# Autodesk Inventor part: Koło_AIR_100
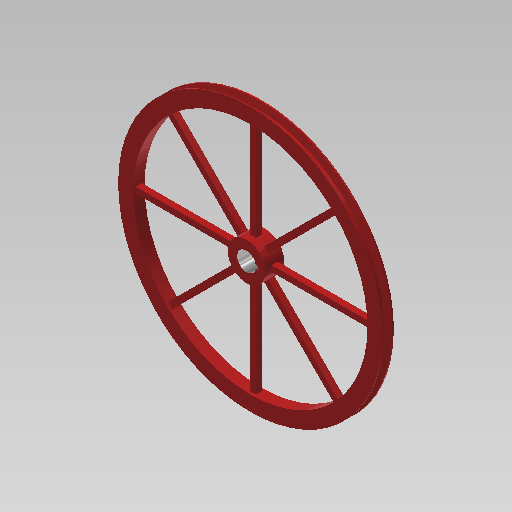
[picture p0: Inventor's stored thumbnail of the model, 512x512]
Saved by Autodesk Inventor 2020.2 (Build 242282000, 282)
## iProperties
Created: 2014-10
Part Number: Koło_AIR_100
Material: Ogólny
Document SubType Name: Modeling
Designer: F.Stasiak
Density: 1 g/cm^3
Appearance: Jasnoczerwona
Mass: 307.16 g
Surface Area: 1307.18 cm^2
Volume: 307.16 cm^3
Catalog Web Link: www.expertbooks.pl
Manager: www.cadconsulting.pl
Company: Fabian Stasiak CAD Consulting
Author: F.Stasiak
Subject: Zbiór ćwiczeń. Autodesk Inventor 2020. Kurs Professional
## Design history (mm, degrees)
sketch "Szkic1"
  geometry: C1 r 12.5 at (0, 0); C2 r 25 at (0, 0); 1 further point
  constraints: 2 centre point, 2 coincident
  dimensions: "d0" = 25 diameter of C1; "d1" = 50 diameter of C2
extrude "Wyciągnięcie proste1" new body sketch "Szkic1" stored distance "d2" = 25; taper "d3" = 0 deg
sketch "Szkic2"
  geometry: C1 r 175 at (0, 0); C2 r 155 at (0, 0); 1 further point
  constraints: 2 centre point, 2 coincident
  dimensions: "d4" = 350 diameter of C1; "d5" = 20 radial gap between concentric circles of C1 C2
extrude "Wyciągnięcie proste2" join sketch "Szkic2" stored distance "d6" = 15; taper "d7" = 0 deg
sketch "Szkic3"
  geometry: L1 (-12.5, -12.5)-(-12.5, 12.5); L2 (-155, -7.5)-(-155, 7.5) reference; L3 (-155, -4)-(-12.5, -4); L4 (-12.5, -4)-(-12.5, 4); L5 (-12.5, 4)-(-155, 4); L6 (-155, 4)-(-155, -4); L7 (-12.5, -12.5)-(-12.5, 12.5) reference; 3 further points
  constraints: 10 end point, 5 midpoint, 2 parallel, 1 horizontal, 1 perpendicular
  dimensions: "d8" = 8 distance between parallel lines of L3 L5
extrude "Wyciągnięcie proste3" join sketch "Szkic3" stored distance "d9" = 8; taper "d10" = 0 deg
pattern_circular "Szyk kołowy1" dims angle "d12" = 360 deg
sketch "Szkic4"
  geometry: L1 (175, -7.5)-(175, 7.5) reference; L2 (175, -5.626)-(165, -4); L3 (165, -4)-(165, 4); L4 (165, 4)-(175, 6.374); L5 (175, 0)-(165, 0); L6 (0, -17.5)-(0, 17.5) reference; 1 further point
  constraints: 8 end point, 2 midpoint, 2 point on line, 1 horizontal, 1 vertical
  dimensions: "d14" = 10 distance of L5.start L5.end; "d15" = 8 distance of L2.end L3.end; "d16" = 12 distance of L4.end L2.start
revolve "Obrót1" sketch "Szkic4" stored, may be unused: angle "d17" = 90 deg
sketch "Szkic6"
  geometry: L1 (0, 2)-(15, 2); L2 (15, 2)-(15, -2); L3 (15, -2)-(0, -2); L4 (0, -2)-(0, 2); 2 further points
  constraints: 8 end point, 2 parallel, 1 coincident, 1 horizontal, 1 midpoint, 1 perpendicular
  dimensions: "d22" = 15 distance of L2.end L3.end; "d23" = 4 distance of L1.end L2.end
extrude "Wyciągnięcie proste5" cut sketch "Szkic6" extent not by distance; stored distance "d24" = 10; taper "d25" = 0 deg
node "Bryła1"
